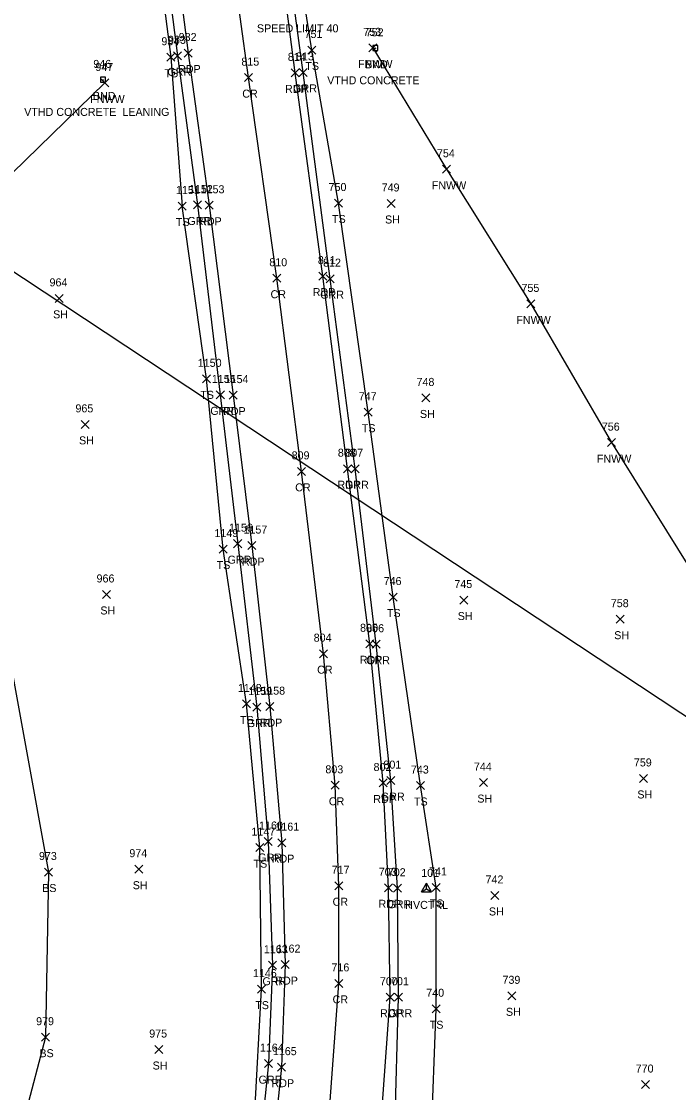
# Model space of a CAD drawing. Extents: x 1629176 to 1637209, y 606063 to 610167.
# Drawn here: x 1629911.4 to 1630075.4, y 607073 to 607340.7 of the extents above; entities that cross this region are included whole.
import ezdxf

# ---------------------------------------------------------------- set-up
doc = ezdxf.new("R2010")
doc.units = 0
for name, color, linetype in [('C_A', 7, 'Continuous'), ('C_I', 7, 'Continuous'), ('CPSM', 7, 'Continuous'), ('DCP', 7, 'Continuous'), ('L_A', 7, 'Continuous'), ('L_I', 7, 'Continuous'), ('L_TIC', 7, 'Continuous'), ('LELB', 7, 'Continuous'), ('LFNC', 7, 'Continuous'), ('M_A', 7, 'Continuous'), ('M_C', 7, 'Continuous'), ('M_I', 7, 'Continuous'), ('MHBP', 7, 'Continuous'), ('P_A', 7, 'Continuous'), ('P_I', 7, 'Continuous'), ('P_TIC', 7, 'Continuous'), ('PET', 7, 'Continuous'), ('PRC', 7, 'Continuous'), ('R_A', 7, 'Continuous'), ('R_I', 7, 'Continuous'), ('R_TIC', 7, 'Continuous'), ('RGR', 7, 'Continuous'), ('S_C', 7, 'Continuous')]:
    doc.layers.add(name, color=color, linetype=linetype)

msp = doc.modelspace()

# ---------------------------------------------------------------- linework, layer by layer
at = {"layer": 'CPSM'}
for p, q in [((1630011.26, 607123.17), (1630012.51, 607125.34)), ((1630013.76, 607123.17), (1630012.51, 607125.34)), ((1630012.51, 607123.9), (1630012.51, 607125.34)), ((1630011.26, 607123.17), (1630012.51, 607123.9)), ((1630011.26, 607123.17), (1630013.76, 607123.17)), ((1630012.51, 607123.9), (1630012.51, 607123.9)), ((1630012.51, 607123.9), (1630013.76, 607123.17))]:
    msp.add_line(p, q, dxfattribs=at)
at = {"layer": 'DCP'}
msp.add_lwpolyline([(1630117.03, 607140.65), (1629896.28, 607286.71)], dxfattribs=at)
at = {"layer": 'L_TIC'}
for points in [[(1629982.84, 607332.53), (1629984.84, 607334.53)], [(1629984.84, 607332.53), (1629982.84, 607334.53)], [(1629998.07, 607333.07), (1630000.07, 607335.07)], [(1630000.07, 607333.07), (1629998.07, 607335.07)], [(1629947.66, 607330.72), (1629949.66, 607332.72)], [(1629949.66, 607330.72), (1629947.66, 607332.72)], [(1629931.18, 607324.29), (1629933.18, 607326.29)], [(1629933.18, 607324.29), (1629931.18, 607326.29)], [(1630016.48, 607302.73), (1630018.48, 607304.73)], [(1630018.48, 607302.73), (1630016.48, 607304.73)], [(1629989.5, 607294.3), (1629991.5, 607296.3)], [(1629991.5, 607294.3), (1629989.5, 607296.3)], [(1630002.67, 607294.18), (1630004.67, 607296.18)], [(1630004.67, 607294.18), (1630002.67, 607296.18)], [(1629950.48, 607293.54), (1629952.48, 607295.54)], [(1629952.48, 607293.54), (1629950.48, 607295.54)], [(1629950.48, 607293.54), (1629952.48, 607295.54)], [(1629952.48, 607293.54), (1629950.48, 607295.54)], [(1629919.78, 607270.47), (1629921.78, 607272.47)], [(1629921.78, 607270.47), (1629919.78, 607272.47)], [(1630037.58, 607269.09), (1630039.58, 607271.09)], [(1630039.58, 607269.09), (1630037.58, 607271.09)], [(1629956.6, 607250.36), (1629958.6, 607252.36)], [(1629958.6, 607250.36), (1629956.6, 607252.36)], [(1630011.37, 607245.59), (1630013.37, 607247.59)], [(1630013.37, 607245.59), (1630011.37, 607247.59)], [(1629996.94, 607242.02), (1629998.94, 607244.02)], [(1629998.94, 607242.02), (1629996.94, 607244.02)], [(1629926.25, 607238.98), (1629928.25, 607240.98)], [(1629928.25, 607238.98), (1629926.25, 607240.98)], [(1630057.7, 607234.42), (1630059.7, 607236.42)], [(1630059.7, 607234.42), (1630057.7, 607236.42)], [(1629960.69, 607207.82), (1629962.69, 607209.82)], [(1629962.69, 607207.82), (1629960.69, 607209.82)], [(1629931.57, 607196.48), (1629933.57, 607198.48)], [(1629933.57, 607196.48), (1629931.57, 607198.48)], [(1630003.22, 607195.84), (1630005.22, 607197.84)], [(1630005.22, 607195.84), (1630003.22, 607197.84)], [(1630020.82, 607195.09), (1630022.82, 607197.09)], [(1630022.82, 607195.09), (1630020.82, 607197.09)], [(1630059.89, 607190.3), (1630061.89, 607192.3)], [(1630061.89, 607190.3), (1630059.89, 607192.3)], [(1629966.52, 607169.11), (1629968.52, 607171.11)], [(1629968.52, 607169.11), (1629966.52, 607171.11)], [(1630025.71, 607149.47), (1630027.71, 607151.47)], [(1630027.71, 607149.47), (1630025.71, 607151.47)], [(1630065.66, 607150.5), (1630067.66, 607152.5)], [(1630067.66, 607150.5), (1630065.66, 607152.5)], [(1630009.97, 607148.73), (1630011.97, 607150.73)], [(1630011.97, 607148.73), (1630009.97, 607150.73)], [(1629969.91, 607133.21), (1629971.91, 607135.21)], [(1629971.91, 607133.21), (1629969.91, 607135.21)], [(1629917.09, 607127.12), (1629919.09, 607129.12)], [(1629919.09, 607127.12), (1629917.09, 607129.12)], [(1629939.66, 607127.82), (1629941.66, 607129.82)], [(1629941.66, 607127.82), (1629939.66, 607129.82)], [(1630013.94, 607123.25), (1630015.94, 607125.25)], [(1630015.94, 607123.25), (1630013.94, 607125.25)], [(1630028.6, 607121.26), (1630030.6, 607123.26)], [(1630030.6, 607121.26), (1630028.6, 607123.26)], [(1629970.34, 607097.85), (1629972.34, 607099.85)], [(1629972.34, 607097.85), (1629970.34, 607099.85)], [(1630032.85, 607096.18), (1630034.85, 607098.18)], [(1630034.85, 607096.18), (1630032.85, 607098.18)], [(1630013.9, 607092.95), (1630015.9, 607094.95)], [(1630015.9, 607092.95), (1630013.9, 607094.95)], [(1629916.39, 607085.84), (1629918.39, 607087.84)], [(1629918.39, 607085.84), (1629916.39, 607087.84)], [(1629944.63, 607082.76), (1629946.63, 607084.76)], [(1629946.63, 607082.76), (1629944.63, 607084.76)], [(1630066.19, 607074.01), (1630068.19, 607076.01)], [(1630068.19, 607074.01), (1630066.19, 607076.01)]]:
    msp.add_lwpolyline(points, dxfattribs=at)
at = {"layer": 'LELB'}
for points in [[(1629901.85, 607620.62), (1629912.64, 607607.29), (1629916.95, 607582.23), (1629921.84, 607547.23), (1629926.69, 607509.97), (1629926.47, 607496.41), (1629932.23, 607463.67), (1629936.65, 607426.68), (1629941.88, 607383.65), (1629948.66, 607331.72), (1629951.48, 607294.54)], [(1629872.74, 607605.4), (1629887.91, 607617.06), (1629901.2, 607617.32), (1629908.5, 607605.8), (1629913.9, 607581.78), (1629917.02, 607546.87), (1629916.16, 607509.81), (1629923.16, 607493.27), (1629925.16, 607453.58), (1629924.47, 607424.14), (1629903.61, 607389.66), (1629905.12, 607348.76), (1629905.7, 607299.56), (1629903.23, 607230.04), (1629906.81, 607190.46), (1629918.09, 607128.12), (1629917.39, 607086.84), (1629912.31, 607067.56), (1629894.57, 607057.72), (1629861.26, 607071.43), (1629823.99, 607082.84), (1629794.36, 607095.25), (1629802.79, 607128.03), (1629840.82, 607119.34)], [(1630084.2, 606935.53), (1630049.16, 606947.36), (1630020.53, 606959.33), (1630006.71, 606971.89), (1629998.15, 606985.2), (1629997.66, 607001.36), (1630003.56, 607031.17), (1630013.65, 607060.81), (1630014.9, 607093.95), (1630014.94, 607124.25), (1630010.97, 607149.73), (1630004.22, 607196.84), (1629997.94, 607243.02), (1629990.5, 607295.3), (1629983.84, 607333.53), (1629977.49, 607374.66), (1629974.09, 607413.89), (1629967.52, 607447.68), (1629960.93, 607485.98), (1629955.08, 607527.79), (1629952.27, 607562.54)], [(1629543.77, 607066.01), (1629589.78, 607058.79), (1629633.94, 607051.49), (1629688.19, 607049.24), (1629712.27, 607039.3), (1629750.85, 607029.57), (1629792.88, 607021.01), (1629837.09, 607010.22), (1629873.61, 607000.62), (1629908.98, 606990.85), (1629926.95, 606990.99), (1629935.68, 606994), (1629949.32, 607001.7), (1629958.17, 607016.23), (1629963.63, 607035.3), (1629969.56, 607066.72), (1629971.34, 607098.85), (1629970.91, 607134.21), (1629967.52, 607170.11), (1629961.69, 607208.82), (1629957.6, 607251.36), (1629951.48, 607294.54)]]:
    msp.add_lwpolyline(points, dxfattribs=at)
at = {"layer": 'LFNC'}
for points in [[(1629999.07, 607334.07), (1630017.48, 607303.73), (1630038.58, 607270.09), (1630058.7, 607235.42), (1630080.65, 607200.1), (1630105.89, 607157.78), (1630113.4, 607146.48), (1630116.93, 607140.46), (1630132.22, 607115.77), (1630142.08, 607097.82), (1630154.89, 607078.39)], [(1629932.18, 607325.29), (1629905.7, 607299.56), (1629894.86, 607289.64), (1629892.4, 607284.76), (1629889.02, 607278.8), (1629873.39, 607261.22), (1629846.96, 607234.11), (1629815.75, 607199.74), (1629791.88, 607173.31), (1629766.82, 607147.57), (1629732.92, 607154.51), (1629676.65, 607165.93), (1629624.92, 607174.61), (1629584.57, 607180.8), (1629561.91, 607184.66)]]:
    msp.add_lwpolyline(points, dxfattribs=at)
at = {"layer": 'MHBP'}
for p, q in [((1630000.34, 607334.62), (1629999.09, 607334.62)), ((1629999.09, 607334.62), (1629999.09, 607333.37)), ((1630000.34, 607334.62), (1629999.09, 607334.62)), ((1629999.09, 607334.62), (1629999.09, 607333.37)), ((1629999.09, 607333.37), (1630000.34, 607333.37)), ((1629999.09, 607333.37), (1630000.34, 607333.37)), ((1630000.34, 607333.37), (1630000.34, 607334.62)), ((1630000.34, 607333.37), (1630000.34, 607334.62)), ((1629932.37, 607326.72), (1629931.12, 607326.72)), ((1629931.12, 607326.72), (1629931.12, 607325.47)), ((1629932.37, 607326.72), (1629931.12, 607326.72)), ((1629931.12, 607326.72), (1629931.12, 607325.47)), ((1629931.12, 607325.47), (1629932.37, 607325.47)), ((1629931.12, 607325.47), (1629932.37, 607325.47)), ((1629932.37, 607325.47), (1629932.37, 607326.72)), ((1629932.37, 607325.47), (1629932.37, 607326.72))]:
    msp.add_line(p, q, dxfattribs=at)
for centre in [(1629999.69, 607333.96), (1629931.72, 607326.05)]:
    msp.add_circle(centre, 0.0833, dxfattribs=at)
at = {"layer": 'P_TIC'}
for points in [[(1629951.98, 607331.78), (1629953.98, 607333.78)], [(1629953.98, 607331.78), (1629951.98, 607333.78)], [(1629978.67, 607326.82), (1629980.67, 607328.82)], [(1629980.67, 607326.82), (1629978.67, 607328.82)], [(1629967.07, 607325.63), (1629969.07, 607327.63)], [(1629969.07, 607325.63), (1629967.07, 607327.63)], [(1629957.23, 607293.73), (1629959.23, 607295.73)], [(1629959.23, 607293.73), (1629957.23, 607295.73)], [(1629974.13, 607275.5), (1629976.13, 607277.5)], [(1629976.13, 607275.5), (1629974.13, 607277.5)], [(1629985.61, 607276.03), (1629987.61, 607278.03)], [(1629987.61, 607276.03), (1629985.61, 607278.03)], [(1629963.22, 607246.29), (1629965.22, 607248.29)], [(1629965.22, 607246.29), (1629963.22, 607248.29)], [(1629980.28, 607227.24), (1629982.28, 607229.24)], [(1629982.28, 607227.24), (1629980.28, 607229.24)], [(1629991.8, 607227.9), (1629993.8, 607229.9)], [(1629993.8, 607227.9), (1629991.8, 607229.9)], [(1629967.92, 607208.69), (1629969.92, 607210.69)], [(1629969.92, 607208.69), (1629967.92, 607210.69)], [(1629997.35, 607184.15), (1629999.35, 607186.15)], [(1629999.35, 607184.15), (1629997.35, 607186.15)], [(1629985.77, 607181.68), (1629987.77, 607183.68)], [(1629987.77, 607181.68), (1629985.77, 607183.68)], [(1629972.36, 607168.44), (1629974.36, 607170.44)], [(1629974.36, 607168.44), (1629972.36, 607170.44)], [(1630000.72, 607149.37), (1630002.72, 607151.37)], [(1630002.72, 607149.37), (1630000.72, 607151.37)], [(1629988.69, 607148.78), (1629990.69, 607150.78)], [(1629990.69, 607148.78), (1629988.69, 607150.78)], [(1629975.37, 607134.45), (1629977.37, 607136.45)], [(1629977.37, 607134.45), (1629975.37, 607136.45)], [(1629989.61, 607123.69), (1629991.61, 607125.69)], [(1629991.61, 607123.69), (1629989.61, 607125.69)], [(1630002.02, 607123.17), (1630004.02, 607125.17)], [(1630004.02, 607123.17), (1630002.02, 607125.17)], [(1629976.25, 607103.98), (1629978.25, 607105.98)], [(1629978.25, 607103.98), (1629976.25, 607105.98)], [(1629989.62, 607099.29), (1629991.62, 607101.29)], [(1629991.62, 607099.29), (1629989.62, 607101.29)], [(1630002.41, 607095.82), (1630004.41, 607097.82)], [(1630004.41, 607095.82), (1630002.41, 607097.82)], [(1629975.31, 607078.35), (1629977.31, 607080.35)], [(1629977.31, 607078.35), (1629975.31, 607080.35)]]:
    msp.add_lwpolyline(points, dxfattribs=at)
at = {"layer": 'PET'}
for points in [[(1629946.3, 607384.48), (1629952.98, 607332.78), (1629958.23, 607294.73), (1629964.22, 607247.29), (1629968.92, 607209.69), (1629973.36, 607169.44), (1629976.37, 607135.45), (1629977.25, 607104.98), (1629976.31, 607079.35), (1629973.81, 607055.42), (1629969.53, 607032.73), (1629964.33, 607014.58), (1629957.85, 607003.11), (1629951.09, 606994.85), (1629937.99, 606987.48), (1629928.54, 606984.14), (1629916.37, 606983.66)], [(1630027.81, 606949.5), (1630014.15, 606956.94), (1630005.77, 606964.44), (1629997.68, 606972.63), (1629992.97, 606983.24), (1629991.03, 606992.52), (1629991.11, 607006.2), (1629997.01, 607037.11), (1630001.08, 607064.64), (1630003.41, 607096.82), (1630003.02, 607124.17), (1630001.72, 607150.37), (1629998.35, 607185.15), (1629992.8, 607228.9), (1629986.61, 607277.03), (1629979.67, 607327.82), (1629973.81, 607373.57)]]:
    msp.add_lwpolyline(points, dxfattribs=at)
at = {"layer": 'PRC'}
msp.add_lwpolyline([(1629963.88, 606969.73), (1629972.76, 606997.52), (1629981.25, 607028.09), (1629988.12, 607066.47), (1629990.62, 607100.29), (1629990.61, 607124.69), (1629989.69, 607149.78), (1629986.77, 607182.68), (1629981.28, 607228.24), (1629975.13, 607276.5), (1629968.07, 607326.63), (1629961.78, 607372.25), (1629956.91, 607408.66), (1629951.88, 607446.34), (1629946.39, 607483.34), (1629940.59, 607526.71), (1629934.53, 607569.1), (1629928.23, 607613.94), (1629922.81, 607653.99), (1629916.48, 607702.82)], dxfattribs=at)
at = {"layer": 'R_TIC'}
for points in [[(1629949.32, 607331.08), (1629951.32, 607333.08)], [(1629951.32, 607331.08), (1629949.32, 607333.08)], [(1629980.73, 607326.94), (1629982.73, 607328.94)], [(1629982.73, 607326.94), (1629980.73, 607328.94)], [(1629954.32, 607293.81), (1629956.32, 607295.81)], [(1629956.32, 607293.81), (1629954.32, 607295.81)], [(1629987.47, 607275.39), (1629989.47, 607277.39)], [(1629989.47, 607275.39), (1629987.47, 607277.39)], [(1629960.02, 607246.36), (1629962.02, 607248.36)], [(1629962.02, 607246.36), (1629960.02, 607248.36)], [(1629993.67, 607227.89), (1629995.67, 607229.89)], [(1629995.67, 607227.89), (1629993.67, 607229.89)], [(1629964.35, 607209.17), (1629966.35, 607211.17)], [(1629966.35, 607209.17), (1629964.35, 607211.17)], [(1629998.95, 607184.04), (1630000.95, 607186.04)], [(1630000.95, 607184.04), (1629998.95, 607186.04)], [(1629969.15, 607168.34), (1629971.15, 607170.34)], [(1629971.15, 607168.34), (1629969.15, 607170.34)], [(1630002.63, 607149.96), (1630004.63, 607151.96)], [(1630004.63, 607149.96), (1630002.63, 607151.96)], [(1629971.95, 607134.74), (1629973.95, 607136.74)], [(1629973.95, 607134.74), (1629971.95, 607136.74)], [(1630004.28, 607123.06), (1630006.28, 607125.06)], [(1630006.28, 607123.06), (1630004.28, 607125.06)], [(1629973.05, 607103.82), (1629975.05, 607105.82)], [(1629975.05, 607103.82), (1629973.05, 607105.82)], [(1630004.51, 607095.84), (1630006.51, 607097.84)], [(1630006.51, 607095.84), (1630004.51, 607097.84)], [(1629972.08, 607079.23), (1629974.08, 607081.23)], [(1629974.08, 607079.23), (1629972.08, 607081.23)]]:
    msp.add_lwpolyline(points, dxfattribs=at)
at = {"layer": 'RGR'}
for points in [[(1630115.67, 606918.76), (1630070.66, 606934.74), (1630047.22, 606943.05), (1630028.22, 606950.43), (1630014.62, 606957.76), (1630006.28, 606964.78), (1629999.39, 606973.89), (1629995.11, 606983.4), (1629993.57, 606992.79), (1629994.69, 607005.74), (1630000.61, 607035.72), (1630004.58, 607063.56), (1630005.51, 607096.84), (1630005.28, 607124.06), (1630003.63, 607150.96), (1629999.95, 607185.04), (1629994.67, 607228.89), (1629988.47, 607276.39), (1629981.73, 607327.94), (1629975.48, 607374.16), (1629971.69, 607411.49)], [(1629943.69, 607384.05), (1629950.32, 607332.08), (1629955.32, 607294.81), (1629961.02, 607247.36), (1629965.35, 607210.17), (1629970.15, 607169.34), (1629972.95, 607135.74), (1629974.05, 607104.82), (1629973.08, 607080.23), (1629970.56, 607055.99), (1629966.4, 607033.17), (1629961.24, 607015.58), (1629955.46, 607004.39), (1629949.06, 606997.06), (1629936.39, 606990.57), (1629926.1, 606987.63), (1629916.88, 606985.75), (1629884.2, 606992.74), (1629842, 607003.78), (1629794.61, 607015.29), (1629751.3, 607025.15), (1629713.98, 607033.77), (1629702.23, 607037.41), (1629690.41, 607042.59)]]:
    msp.add_lwpolyline(points, dxfattribs=at)

# ---------------------------------------------------------------- texts
at = {"layer": 'C_A'}
msp.add_text('HVCTRL', height=2, dxfattribs=at).set_placement((1630007.2, 607118.9))
at = {"layer": 'C_I'}
msp.add_text('101', height=2, dxfattribs=at).set_placement((1630011.2, 607126.9))
at = {"layer": 'L_A'}
for s, p in [('FNWW', (1629995.41, 607329.07)), ('TS', (1629947.07, 607326.72)), ('TS', (1629982.25, 607328.53)), ('FNWW', (1629928.52, 607320.29)), ('FNWW', (1630013.82, 607298.73)), ('TS', (1629949.89, 607289.54)), ('TS', (1629949.89, 607289.54)), ('TS', (1629988.91, 607290.3)), ('SH', (1630002.15, 607290.18)), ('SH', (1629919.27, 607266.47)), ('FNWW', (1630034.93, 607265.09)), ('TS', (1629956.01, 607246.36)), ('SH', (1630010.86, 607241.59)), ('TS', (1629996.35, 607238.02)), ('SH', (1629925.74, 607234.98)), ('FNWW', (1630055.05, 607230.42)), ('TS', (1629960.1, 607203.82)), ('SH', (1629931.06, 607192.48)), ('TS', (1630002.63, 607191.84)), ('SH', (1630020.31, 607191.09)), ('SH', (1630059.38, 607186.3)), ('TS', (1629965.93, 607165.11)), ('TS', (1630009.38, 607144.73)), ('SH', (1630025.2, 607145.47)), ('SH', (1630065.15, 607146.5)), ('TS', (1629969.32, 607129.21)), ('BS', (1629916.53, 607123.12)), ('SH', (1629939.15, 607123.82)), ('TS', (1630013.35, 607119.25)), ('SH', (1630028.09, 607117.26)), ('TS', (1629969.75, 607093.85)), ('SH', (1630032.34, 607092.18)), ('TS', (1630013.31, 607088.95)), ('BS', (1629915.84, 607081.84)), ('SH', (1629944.11, 607078.76))]:
    msp.add_text(s, height=2, dxfattribs=at).set_placement(p)
at = {"layer": 'L_I'}
for s, p in [('753', (1629996.71, 607337.07)), ('934', (1629946.3, 607334.72)), ('751', (1629982.04, 607336.53)), ('947', (1629929.81, 607328.29)), ('754', (1630015.11, 607306.73)), ('1151', (1629949.93, 607297.54)), ('1151', (1629949.93, 607297.54)), ('750', (1629988.05, 607298.3)), ('749', (1630001.3, 607298.18)), ('964', (1629918.37, 607274.47)), ('755', (1630036.22, 607273.09)), ('1150', (1629955.39, 607254.36)), ('748', (1630010.01, 607249.59)), ('747', (1629995.58, 607246.02)), ('965', (1629924.84, 607242.98)), ('756', (1630056.28, 607238.42)), ('1149', (1629959.55, 607211.82)), ('966', (1629930.11, 607200.48)), ('746', (1630001.8, 607199.84)), ('745', (1630019.46, 607199.09)), ('758', (1630058.53, 607194.3)), ('1148', (1629965.4, 607173.11)), ('743', (1630008.61, 607152.73)), ('744', (1630024.35, 607153.47)), ('759', (1630064.29, 607154.5)), ('1147', (1629968.78, 607137.21)), ('973', (1629915.73, 607131.12)), ('974', (1629938.3, 607131.82)), ('741', (1630013.14, 607127.25)), ('742', (1630027.24, 607125.26)), ('1146', (1629969.16, 607101.85)), ('739', (1630031.48, 607100.18)), ('740', (1630012.45, 607096.95)), ('979', (1629915.02, 607089.84)), ('975', (1629943.26, 607086.76)), ('770', (1630064.74, 607078.01))]:
    msp.add_text(s, height=2, dxfattribs=at).set_placement(p)
at = {"layer": 'M_A'}
for p in [(1629997.18, 607328.96), (1629929.21, 607321.06)]:
    msp.add_text('BND', height=2, dxfattribs=at).set_placement(p)
at = {"layer": 'M_C'}
for s, p in [('VTHD CONCRETE', (1629987.71, 607324.96)), ('VTHD CONCRETE  LEANING', (1629912.04, 607317.06))]:
    msp.add_text(s, height=2, dxfattribs=at).set_placement(p)
at = {"layer": 'M_I'}
for s, p in [('752', (1629997.33, 607336.96)), ('946', (1629929.3, 607329.06))]:
    msp.add_text(s, height=2, dxfattribs=at).set_placement(p)
at = {"layer": 'P_A'}
for s, p in [('RDP', (1629950.47, 607327.78)), ('CR', (1629966.5, 607321.63)), ('RDP', (1629977.16, 607322.82)), ('RDP', (1629955.72, 607289.73)), ('CR', (1629973.56, 607271.5)), ('RDP', (1629984.09, 607272.03)), ('RDP', (1629961.7, 607242.29)), ('CR', (1629979.71, 607223.24)), ('RDP', (1629990.28, 607223.9)), ('RDP', (1629966.41, 607204.69)), ('RDP', (1629995.84, 607180.15)), ('CR', (1629985.2, 607177.68)), ('RDP', (1629970.85, 607164.44)), ('CR', (1629988.12, 607144.78)), ('RDP', (1629999.21, 607145.37)), ('RDP', (1629973.86, 607130.45)), ('CR', (1629989.05, 607119.69)), ('RDP', (1630000.51, 607119.17)), ('RDP', (1629974.74, 607099.98)), ('CR', (1629989.05, 607095.29)), ('RDP', (1630000.9, 607091.82)), ('RDP', (1629973.8, 607074.35))]:
    msp.add_text(s, height=2, dxfattribs=at).set_placement(p)
at = {"layer": 'P_I'}
for s, p in [('932', (1629950.62, 607335.78)), ('815', (1629966.27, 607329.63)), ('814', (1629977.87, 607330.82)), ('1153', (1629956.1, 607297.73)), ('810', (1629973.25, 607279.5)), ('811', (1629985.38, 607280.03)), ('1154', (1629962.09, 607250.29)), ('809', (1629978.83, 607231.24)), ('808', (1629990.36, 607231.9)), ('1157', (1629966.8, 607212.69)), ('805', (1629995.91, 607188.15)), ('804', (1629984.33, 607185.68)), ('1158', (1629971.24, 607172.44)), ('803', (1629987.25, 607152.78)), ('802', (1629999.28, 607153.37)), ('1161', (1629974.77, 607138.45)), ('717', (1629988.82, 607127.69)), ('703', (1630000.58, 607127.17)), ('1162', (1629975.08, 607107.98)), ('716', (1629988.77, 607103.29)), ('700', (1630000.88, 607099.82)), ('1165', (1629974.14, 607082.35))]:
    msp.add_text(s, height=2, dxfattribs=at).set_placement(p)
at = {"layer": 'R_A'}
for p in [(1629947.8, 607327.08), (1629979.22, 607322.94), (1629952.8, 607289.81), (1629985.96, 607271.39), (1629958.51, 607242.36), (1629992.16, 607223.89), (1629962.84, 607205.17), (1629997.44, 607180.04), (1629967.64, 607164.34), (1630001.12, 607145.96), (1629970.44, 607130.74), (1630002.77, 607119.06), (1629971.54, 607099.82), (1630003, 607091.84), (1629970.57, 607075.23)]:
    msp.add_text('GRR', height=2, dxfattribs=at).set_placement(p)
at = {"layer": 'R_I'}
for s, p in [('933', (1629947.95, 607335.08)), ('813', (1629979.93, 607330.94)), ('1152', (1629953.19, 607297.81)), ('812', (1629986.67, 607279.39)), ('1155', (1629958.9, 607250.36)), ('807', (1629992.23, 607231.89)), ('1156', (1629963.17, 607213.17)), ('806', (1629997.45, 607188.04)), ('1159', (1629968.01, 607172.34)), ('801', (1630001.75, 607153.96)), ('1160', (1629970.69, 607138.74)), ('702', (1630002.84, 607127.06)), ('1163', (1629971.88, 607107.82)), ('701', (1630003.64, 607099.84)), ('1164', (1629970.9, 607083.23))]:
    msp.add_text(s, height=2, dxfattribs=at).set_placement(p)
at = {"layer": 'S_C'}
msp.add_text('SPEED LIMIT 40', height=2, dxfattribs=at).set_placement((1629970.16, 607337.95))

doc.saveas('drawing.dxf')
